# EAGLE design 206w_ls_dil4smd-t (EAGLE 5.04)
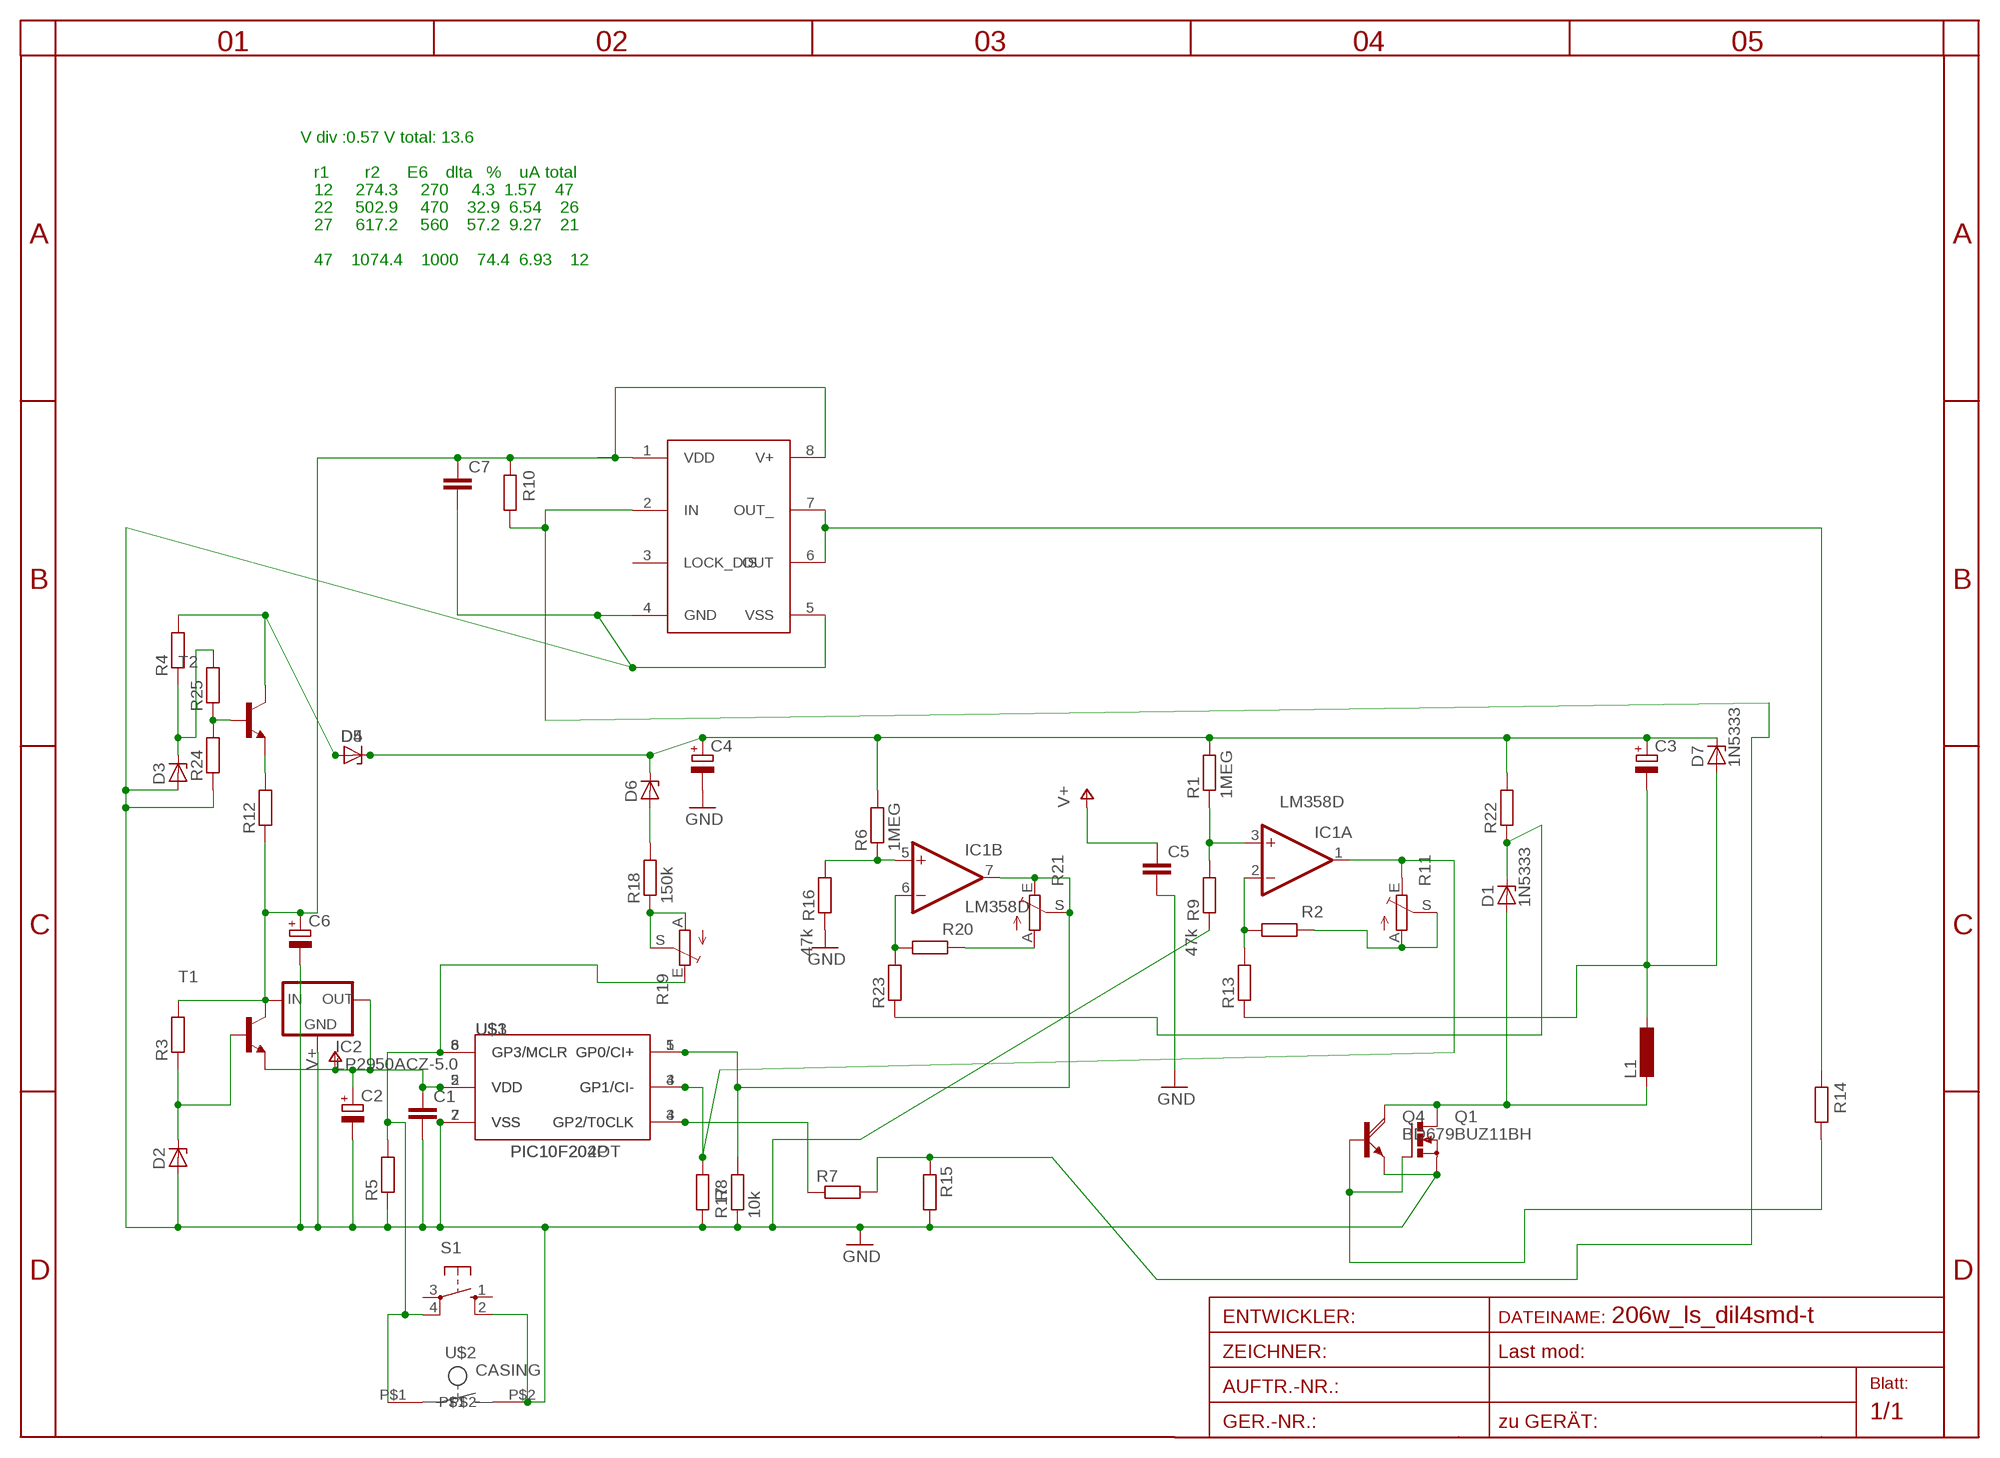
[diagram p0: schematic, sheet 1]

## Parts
C1  C-EUC1206  [C1206]
C2  CPOL-EUSANYO_SMD_E12  [SANYO-OSCON_SMD_E12]
C3  CPOL-EUE5-8.5  [E5-8,5]
C4  CPOL-EUE5-8.5  [E5-8,5]
C5  C-EUC1206  [C1206]
C6  CPOL-EUSANYO_SMD_E12  [SANYO-OSCON_SMD_E12]
C7  C-EUC1206  [C1206]
D1  1N5333  [C1702-15]
D2  ZENER-DIODESOT23  [SOT23]
D3  ZENER-DIODESMB  [SMB]
D4  ZENER-DIODESMB  [SMB]
D5  ZENER-DIODESMB  [SMB]
D6  ZENER-DIODESMB  [SMB]
D7  1N5333  [C1702-15]
IC1  LM358D  [SO08]
IC2  LP2950ACZ-5.0  [TO92]
IC3  TC4432X  [SO-08]
L1  L-EU2200-15.24  [2200-15.24]
Q1  BUZ11BH  [TO220BH]
Q4  BD679  [TO126AV]
R1  1MEG  R-EU_R1206  [R1206]
R2  R-EU_R0805  [R0805]
R3  R-EU_R0805  [R0805]
R4  R-EU_R0805  [R0805]
R5  R-EU_R0805  [R0805]
R6  1MEG  R-EU_R1206  [R1206]
R7  R-EU_R0805  [R0805]
R8  R-EU_R0805  [R0805]
R9  47k  R-EU_R0805  [R0805]
R10  R-EU_R0805  [R0805]
R11  TRIM_EU-CA6V  [CA6V]
R12  R-EU_R0805  [R0805]
R13  R-EU_R1206  [R1206]
R14  R-EU_0207/10  [0207/10]
R15  R-EU_R0805  [R0805]
R16  47k  R-EU_R0805  [R0805]
R17  10k  R-EU_R0805  [R0805]
R18  150k  R-EU_R1206  [R1206]
R19  TRIM_EU-CA6V  [CA6V]
R20  R-EU_R0805  [R0805]
R21  TRIM_EU-CA6V  [CA6V]
R22  R-EU_0309/12  [0309/12]
R23  R-EU_R1206  [R1206]
R24  R-EU_R0805  [R0805]
R25  R-EU_R0805  [R0805]
S1  10-XX  [B3F-10XX]
T1  BC846BLT1-NPN-SOT23-BEC  [SOT23-BEC]
T2  BC846BLT1-NPN-SOT23-BEC  [SOT23-BEC]
U$1  PIC10F202OT  [SOT23-6]
U$2  CASING  [CASING]
U$3  PIC10F204P  [DIL8]

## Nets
BB: IC3.2(IN) R7.2 R10.1 R15.1
GATE: Q1.G Q4.B R14.1
GND: C1.2 C2.- C4.- C5.2 C6.- C7.2 D2.1(A) D3.A IC2.2(GND) IC3.4(GND) IC3.5(VSS) Q1.S Q4.E R5.1 R8.1 R9.1 R15.2 R16.1 R17.1 R24.1 S1.2(S1) U$1.2(VSS) U$2.P$2 U$3.7(VSS)
HOT2: D1.C R22.1 R23.1
HOTSPOT: D1.A L1.2 Q1.D Q4.C
N$1: R2.1 R11.A R11.S
N$2: IC1.1(A:OUT) R8.2 R11.E U$1.3(GP1/CI-) U$3.4(GP1/CI-)
N$5: IC1.5(B:+IN) R6.1 R16.2
N$6: D2.3(C) R3.1 T1.B
N$7: R5.2 R19.E S1.4(P1) U$1.6(GP3/MCLR) U$2.P$1 U$3.8(GP3/MCLR)
N$8: IC1.3(A:+IN) R1.1 R9.2
N$9: R7.1 U$1.4(GP2/T0CLK) U$3.3(GP2/T0CLK)
N$10: R24.2 R25.1 T2.B
N$11: IC3.6(OUT) IC3.7(OUT_) R14.2
N$12: D3.C R4.1 R25.2
N$13: R18.1 R19.A R19.S
N$14: IC1.7(B:OUT) R17.2 R21.E R21.S U$1.1(GP0/CI+) U$3.5(GP0/CI+)
N$15: IC1.2(A:-IN) R2.2 R13.2
N$21: D4.A D5.A R4.2 T2.C
N$22: R12.2 T2.E
N$23: D6.A R18.2
N$24: IC1.6(B:-IN) R20.2 R23.2
N$25: R20.1 R21.A
V60: C3.+ C4.+ D4.C D5.C D6.C D7.C R1.2 R6.2 R22.2
V+: C1.1 C2.+ C5.1 IC2.1(OUT) T1.E U$1.5(VDD) U$3.2(VDD)
VCC: C6.+ C7.1 IC2.3(IN) IC3.1(VDD) IC3.8(V+) R3.2 R10.2 R12.1 T1.C
VOUT: C3.- D7.A L1.1 R13.1
Unconnected: IC3.3(LOCK_DIS) S1.1(S) S1.3(P)

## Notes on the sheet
- V div :0.57 V total: 13.6
- r1        r2      E6    dlta   %    uA total
- 12     274.3     270     4.3  1.57    47
- 22     502.9     470    32.9  6.54    26
- 27     617.2     560    57.2  9.27    21
- 47    1074.4    1000    74.4  6.93    12

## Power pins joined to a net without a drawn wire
GND: IC1.4(P:V-)
V+: IC1.8(P:V+)

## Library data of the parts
C1 C5 C7 = rcl:C-EU: CAPACITOR, European symbol
C2-C4 C6 = rcl:CPOL-EU: POLARIZED CAPACITOR, European symbol
D1 D7 = diode-1:1N5333: Z DIODE
D2-D6 = diode-1:ZENER-DIODE: Z-Diode
IC1 = linear4:LM358: OP AMP
IC2 = v-reg:LP2950?*: Source: http://cache.national.com/ds/LP/LP2950.pdf
IC3 = microchip:TC4432
L1 = rcl:L-EU: INDUCTOR, European symbol
Q1 = transistor-power:BUZ11: N-CHANNEL MOS FET
Q4 = transistor-power:BD679: NPN DARLINGTON TRANSISTOR
R1-R6 R8-R10 R12 R14-R16 R20 R24 R25 = rcl:R-EU_: RESISTOR, European symbol
R7 R13 R17 R18 R22 R23 = rcl-2:R-EU_: RESISTOR, European symbol
R11 R19 R21 = pot:TRIM_EU-: POTENTIOMETER
S1 = switch-omron:10-XX: OMRON SWITCH
T1 T2 = transistor-neu-to92:*-NPN-: NPN Transistror
U$1 U$3 = microchip-5:PIC10F2*: uPC nW 0,25/0,5k Program Flash memory Comparator
U$2 = button:CASING

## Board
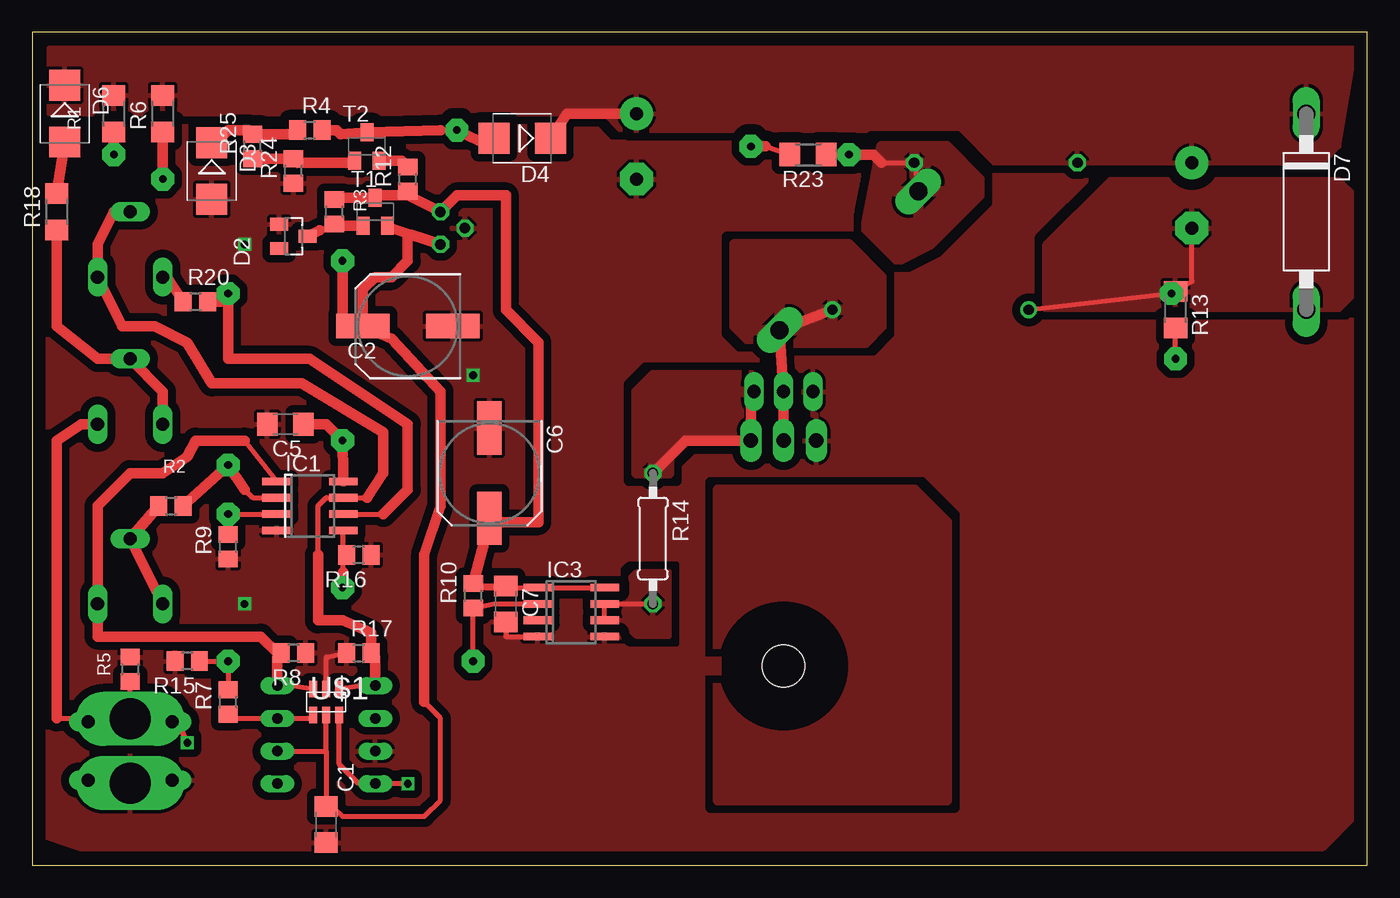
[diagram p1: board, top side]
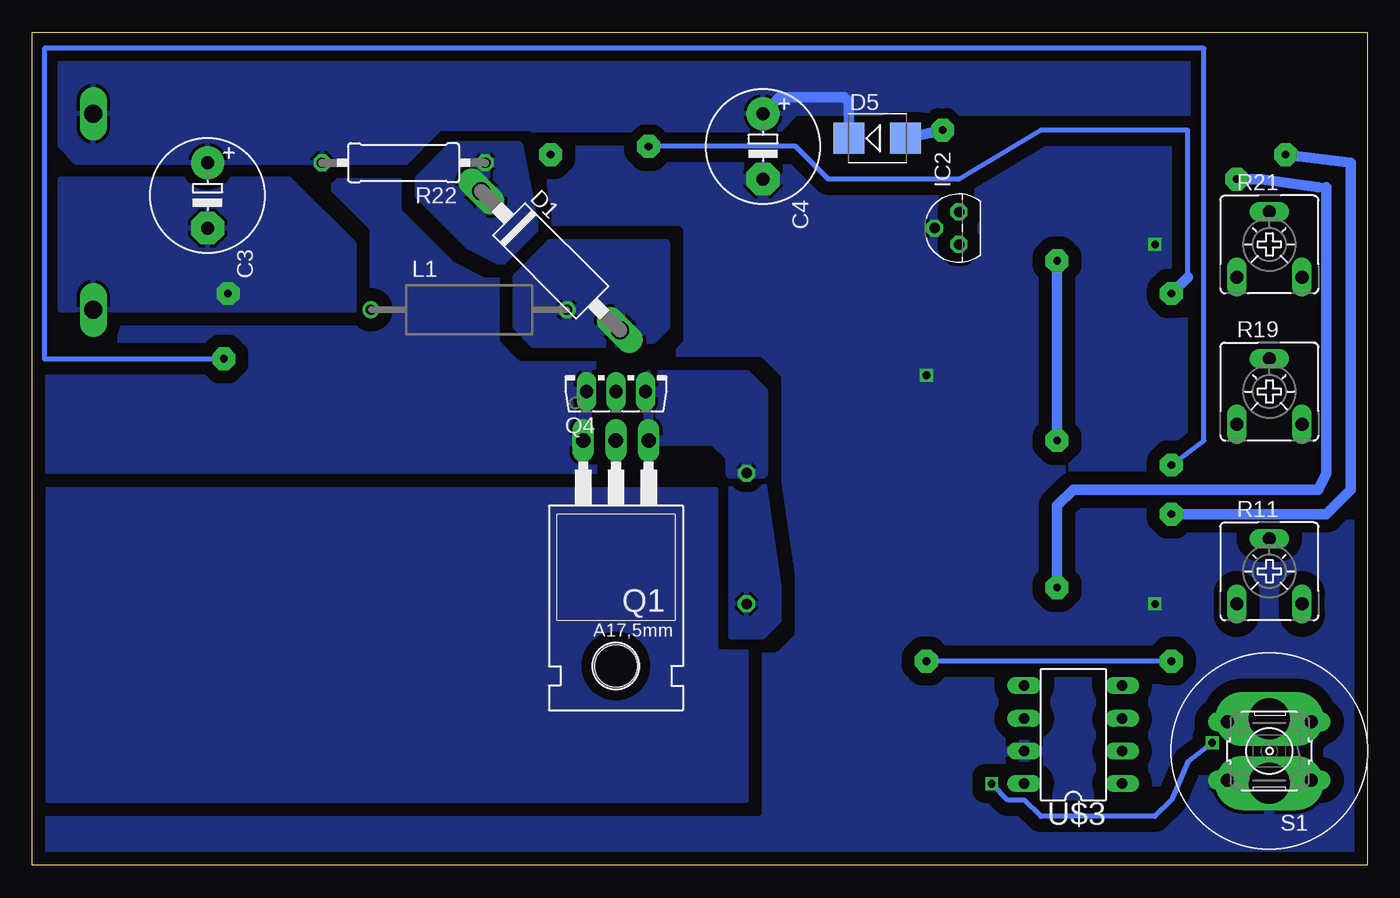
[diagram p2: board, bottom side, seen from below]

Size 103.81 x 64.76 mm. Coordinates in mm from the lower left corner, seen from the top.
Outline: 0,0 103.81,0 103.81,64.76 0,64.76 0,0
Copper layers (1*16): Top 0.035mm / dielectric 1.5mm / Bottom 0.035mm
Design rules "default": minimum track width 10mil, minimum drill 24mil, track to track 8mil, track to pad 8mil, pad to pad 8mil, via to via 8mil, smd to smd 8mil, copper to edge 40mil, drill to drill 8mil, minimum pad ring 10mil, minimum via ring 8mil, stop-mask expansion 4mil, vias tented up to drill 0mil, thermal gap 10mil

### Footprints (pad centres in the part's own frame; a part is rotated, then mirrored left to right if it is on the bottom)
C1206 = smd 1.6 x 1.8: 1 -1.4,0; 2 1.4,0
SANYO-OSCON_SMD_E12 = smd 4.15 x 1.9: + 3.5,0; - -3.5,0
E5-8,5 = drill 1.016 pad 2.54 round: + -2.54,0 | drill 1.016 pad 2.54 octagon: - 2.54,0
C1702-15 = drill 1.397 long: A 7.62,0; C -7.62,0
SOT23 = smd 1 x 1.4: 1 -0.95,-1.1; 2 0.95,-1.1; 3 0,1.1
SMB = smd 2.4 x 2.4: A 2.2,0; C -2.2,0
SO08 = smd 0.6 x 2.2: 1 -1.905,-2.6; 2 -0.635,-2.6; 3 0.635,-2.6; 4 1.905,-2.6; 5 1.905,2.6; 6 0.635,2.6; 7 -0.635,2.6; 8 -1.905,2.6
TO92 = drill 0.813 octagon: 1 -1.27,0; 2 0,1.905; 3 1.27,0
SO-08 = smd 0.6 x 2.2: 1 -1.905,-2.6; 2 -0.635,-2.6; 3 0.635,-2.6; 4 1.905,-2.6; 5 1.905,2.6; 6 0.635,2.6; 7 -0.635,2.6; 8 -1.905,2.6
2200-15.24 = drill 0.8 pad 1.27 round: 1 -7.62,0; 2 7.62,0
TO220BH = drill 1.118 long: D 0,-6.35; G -2.54,-6.35; S 2.54,-6.35 | hole 3.302: 0,11.176
TO126AV = drill 1.016 long: B 2.286,-1.27; C 0,-1.27; E -2.286,-1.27
R1206 = smd 1.6 x 1.803: 1 -1.422,0; 2 1.422,0
R0805 = smd 1.3 x 1.5: 1 -0.95,0; 2 0.95,0
CA6V = drill 1.016 long: A -2.54,-2.54; E 2.54,-2.54; S 0,2.54
0207/10 = drill 0.813 octagon: 1 -5.08,0; 2 5.08,0
0309/12 = drill 0.813 octagon: 1 -6.35,0; 2 6.35,0
B3F-10XX = drill 1.016 long: 1 -3.251,2.261; 2 3.251,2.261; 3 -3.251,-2.261; 4 3.251,-2.261
SOT23-BEC = smd 1 x 1.4: B -0.95,-1.1; C 0,1.1; E 0.95,-1.1
SOT23-6 = smd 0.635 x 1.27: 1 -1.016,-1.016; 2 0,-1.016; 3 1.016,-1.016; 4 1.016,1.016; 5 0,1.016; 6 -1.016,1.016
CASING = drill 3.2 pad 3.81 long: P$1 -2.5,0; P$2 2.5,0
DIL8 = drill 0.813 long: 1 -3.81,-3.81; 2 -1.27,-3.81; 3 1.27,-3.81; 4 3.81,-3.81; 5 3.81,3.81; 6 1.27,3.81; 7 -1.27,3.81; 8 -3.81,3.81

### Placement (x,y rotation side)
C1  22.86,3.17 270 top
C2  29.21,41.91 180 top
C3  90.17,52.07 270 bottom
C4  46.99,55.88 270 bottom
C5  19.68,34.29 180 top
C6  35.56,30.48 270 top
C7  36.83,20.32 270 top
D1  63.5,46.99 315 bottom
D2  20.32,48.9 270 top
D3  13.97,53.98 270 top
D4  38.1,56.52 180 top
D5  38.1,56.52 0 bottom
D6  2.54,58.42 270 top
D7  99.06,50.8 270 top
IC1  21.59,27.94 270 top
IC2  31.75,49.53 90 bottom
IC3  41.91,19.68 270 top
L1  69.85,43.18 0 bottom
Q1  58.42,26.67 180 bottom
Q4  58.42,38.1 0 bottom
R1  6.35,58.42 90 top
R2  10.79,27.94 0 top
R3  23.5,50.8 90 top
R4  21.59,57.15 0 top
R5  7.62,15.24 270 top
R6  10.16,58.42 90 top
R7  15.24,12.7 90 top
R8  20.32,16.51 180 top
R9  15.24,24.77 90 top
R10  34.29,20.95 90 top
R11  7.62,22.86 0 bottom
R12  29.21,53.34 90 top
R13  88.9,43.18 270 top
R14  48.26,25.4 270 top
R15  12.06,15.88 180 top
R16  25.4,24.13 180 top
R17  25.4,16.51 0 top
R18  1.91,50.8 90 top
R19  7.62,36.83 0 bottom
R20  12.7,43.81 0 top
R21  7.62,48.26 0 bottom
R22  74.93,54.61 180 bottom
R23  60.33,55.24 180 top
R24  20.32,53.98 90 top
R25  17.14,55.88 90 top
S1  7.62,8.89 180 bottom
T1  26.67,50.8 0 top
T2  26.04,55.88 0 top
U$1  22.86,12.7 180 top
U$2  7.62,8.89 270 bottom
U$3  22.86,10.16 90 bottom

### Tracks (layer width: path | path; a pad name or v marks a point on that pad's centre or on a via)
BB  (via drill 0.6 pad 1.78)
  Top 0.406: IC3.2 35.88,20.32 R10.1 v34.29,15.88 | R7.2 v15.24,15.88 R15.1
  Bottom 0.406: v15.24,15.88 v34.29,15.88
GATE
  Top 0.406: 55.88,36.58 Q4.B
  Top 0.813: R14.1 50.8,33.02 Q1.G 55.88,36.58
  pour Top: 55.88,38.1 48.26,38.1 46.99,36.83 46.99,30.48 49.53,30.48 49.53,31.75 50.8,33.02 55.88,33.02
  pour Bottom: 55.88,38.1 48.26,38.1 46.99,36.83 46.99,30.48 49.53,30.48 49.53,31.75 50.8,33.02 55.88,33.02
GND  (via drill 0.6)
  Top 0.406: C7.2 36.83,17.78 IC3.4 | U$1.2 22.86,16.19 R17.1
  other vias: 16.51,48.26 16.51,20.32 34.29,38.1
  pour Bottom (isolate 1.016, rank 5): 102.87,60.96 102.87,0 90.17,0 1.27,1.27 1.27,53.34 1.27,58.42
  pour Top (isolate 0.61, rank 5): 1.27,63.5 99.06,63.5 102.87,59.69 102.87,3.81 100.33,1.27 3.81,1.27 0,2.54
HOT2  (via drill 0.6 pad 1.78)
  Top 0.406: R23.1 v63.5,55.24 | 66.04,54.61 R22.1 D1.C
  Top 0.813: v63.5,55.24 65.41,55.24 66.04,54.61
  pour Top (rank 2): 66.04,55.88 71.12,55.88 73.66,53.34 73.66,52.07 69.85,48.26 67.31,46.99 64.77,49.53
  pour Bottom (rank 2): 66.04,55.88 71.12,55.88 73.66,53.34 73.66,52.07 69.85,48.26 67.31,46.99 64.77,49.53
HOTSPOT
  Top 0.813: L1.2 D1.A Q4.C Q1.D
  pour Top: 54.61,48.26 63.5,48.26 66.04,45.72 66.04,41.91 64.77,40.64 55.88,40.64 54.61,41.91
  pour Bottom: 54.61,48.26 63.5,48.26 66.04,45.72 66.04,41.91 64.77,40.64 55.88,40.64 54.61,41.91
N$1
  Top 0.813: R11.A R11.S R2.1
N$2
  Top 0.406: 16.51,33.02 IC1.1 | U$1.3 20.32,13.97 U$3.4 | 19.05,16.19 R8.2 19.05,16.51
  Top 0.813: 16.51,33.02 12.7,33.02 12.06,31.75 10.16,30.48 7.62,30.48 5.08,27.94 R11.E 5.08,17.78 17.78,17.78 19.05,16.51 | 19.05,16.19 U$3.4
N$5  (via drill 0.6 pad 1.78)
  Top 0.406: 24.19,24.39 R16.2 | 24.19,22.8 24.19,24.39 | 24.19,24.39 IC1.5
  Top 0.813: v10.16,53.34 R6.1 | v24.13,21.59 24.19,22.8
  Bottom 0.61: 3.17,52.7 3.81,52.7
  Bottom 0.813: v10.16,53.34 8.26,53.34 3.81,52.7 | 3.17,52.7 3.17,30.48 3.81,29.21 22.86,29.21 24.13,27.94 v24.13,21.59
N$6
  Top 0.406: 23.64,49.7 R3.1 22.37,49.36
  Top 0.813: 23.64,49.7 T1.B | D2.3 22.37,49.36
N$7  (via drill 0.6)
  Top 0.406: 1.91,11.43 7.58,11.43 U$2.P$1 | U$2.P$1 10.79,10.79 10.16,10.44 S1.4 11.15,11.43 v12.06,9.53 | U$1.6 23.88,7.87 25.4,6.35 U$3.8 v29.21,6.35 | U$2.P$1 R5.2
  Top 0.813: R19.E 3.81,34.29 1.91,33.02 1.91,11.43
  Bottom 0.406: v29.21,6.35 27.94,5.08 26.67,5.08 25.4,3.81 16.51,3.81 15.24,5.08 13.97,8.05 v12.06,9.53
N$8  (via drill 0.6 pad 1.78)
  Top 0.406: IC1.3 15.56,27.3 R9.2 v15.24,27.3
  Top 0.813: v6.35,55.24 R1.1
  Bottom 0.813: v6.35,55.24 1.27,54.61 1.27,29.21 3.17,27.3 v15.24,27.3
N$9
  Top 0.406: R7.1 15.56,11.43 U$3.3 21.59,11.43 U$1.4
N$10
  Top 0.406: 24.77,54.61 T2.B
  Top 0.813: 24.77,54.61 20.64,54.61 R24.2 R25.1
N$11
  Top 0.406: R14.2 IC3.7 IC3.6
  pour Bottom (isolate 0.813): 45.72,21.59 46.99,30.48 49.53,30.48 49.53,17.78 46.99,17.78 45.72,19.05
  pour Top (isolate 0.813): 45.72,21.59 46.99,22.86 49.53,22.86 49.53,17.78 46.99,17.78 45.72,19.05
N$12
  Top 0.406: D3.C 13.97,55.88
  Top 0.813: D3.C 14.27,56.17 15.24,57.15 16.82,57.15 R25.2 20.32,56.83 R4.1
N$13
  Top 0.813: R18.1 1.91,41.91 5.08,39.37 R19.S 10.16,36.83 R19.A
N$14
  Top 0.406: 26.04,28.57 IC1.7 22.86,28.57 22.23,27.94 22.23,24.13 | 26.67,16.19 R17.2 | U$1.1 25.4,13.97 U$3.5
  Top 0.813: 26.04,28.57 27.3,30.48 27.3,33.66 20.95,37.47 13.97,37.47 12.06,40.64 9.53,41.91 6.99,41.91 R21.E 5.08,48.26 6.35,50.8 R21.S | R17.2 26.35,18.1 24.13,19.05 22.23,19.05 22.23,24.13 | U$3.5 26.67,16.19
N$15  (via drill 0.6 pad 1.78)
  Top 0.406: 16.51,29.21 17.14,28.57 IC1.2 | v88.9,39.37 R13.2
  Top 0.813: 16.51,29.21 v15.24,31.11 R2.2
  Bottom 0.406: v88.9,39.37 102.87,39.37 102.87,63.5 12.7,63.5 12.7,33.02 v15.24,31.11
N$20
  pour Top (isolate 0.813, rank 3): 53.34,29.21 68.58,29.21 71.12,26.67 71.12,5.08 53.34,5.08
  pour Bottom (isolate 0.813, rank 3): 48.26,29.21 102.87,29.21 102.87,5.08 48.26,5.08
N$21  (via drill 0.6 pad 1.78)
  Top 0.406: 35.56,55.88 D5.A | 31.75,57.15 v33.02,57.15
  Top 0.813: v33.02,57.15 35.56,55.88 | 31.75,57.15 T2.C 23.98,56.83 23.66,57.15 R4.2
  Bottom 0.813: v33.02,57.15 D5.A
N$22
  Top 0.813: T2.E 28.72,54.78 R12.2
N$23
  Top 0.813: R18.2 D6.A
N$24  (via drill 0.6 pad 1.78)
  Top 0.406: 57,55.88 R23.2 | IC1.6 27.3,27.3
  Top 0.813: v55.88,55.88 57,55.88 | 27.3,27.3 29.21,29.21 29.21,34.29 21.59,39.37 15.24,39.37 v15.24,44.45 14.61,43.81 R20.2
  Bottom 0.406: v55.88,55.88 44.45,55.88 41.91,53.34 31.75,53.34 25.4,57.15 13.97,57.15 13.97,45.72
  Bottom 0.813: v15.24,44.45 13.97,45.72
N$25
  Top 0.813: R21.A 10.48,45.72 R20.1
V60
  Top 0.813: C4.+ 41.57,58.42 D5.C
  Bottom 0.813: D5.C 40.3,59.35 40.64,59.69 45.72,59.69 C4.+
  pour Top (isolate 0.813, rank 4): 102.87,63.5 1.27,63.5 1.27,58.42 44.45,58.42 45.72,57.15 71.12,57.15 73.66,54.61 100.33,54.61 101.6,55.88
  pour Bottom (isolate 0.813, rank 4): 102.87,63.5 1.27,63.5 1.27,48.26 7.62,48.26 7.62,54.61 6.35,55.88 6.35,57.15 7.62,58.42 44.45,58.42 45.72,57.15 71.12,57.15 73.66,54.61 100.33,54.61 101.6,55.88
V+  (via drill 0.6 pad 1.78)
  Top 0.406: C2.+ 24.13,41.91 | IC1.8 24.13,29.91 | 27.94,49.53 T1.E | U$3.2 22.86,8.89 | 22.86,8.89 U$1.5 | 30.48,12.7 31.75,11.43 31.75,5.08 30.48,3.81 24.13,3.81 23.5,4.45 22.99,4.45 C1.1 22.86,8.89
  Top 0.813: 27.79,49.53 27.94,49.53 29.46,49.02 | 29.46,49.02 IC2.1 | 30.48,12.7 30.48,24.13 31.75,27.94 31.75,36.83 27.94,40.95 C2.+ 25.71,44.76 26.67,45.72 27.94,45.72 29.21,46.99 29.21,48.77 29.46,49.02 | IC1.8 24.19,30.42 v24.13,33.02 22.86,34.29 C5.1 | 24.13,41.91 v24.13,46.99
  Bottom 0.813: v24.13,46.99 v24.13,33.02
VCC
  Top 0.406: IC3.8 IC3.1 35.24,21.59 R10.2 34.29,21.72 C7.1 | 35.56,26.67 C6.+ | 26.84,52.07 T1.C | 23.64,51.9 R3.2
  Top 0.813: R10.2 35.56,26.67 39.37,26.67 39.37,40.64 36.83,43.18 36.83,52.07 33.02,52.07 IC2.3 29.21,52.07 | T1.C 23.64,51.9 | 29.21,52.07 26.84,52.07 | 29.21,52.07 R12.1
VOUT  (via drill 0.6 pad 1.78)
  Top 0.406: L1.1 v88.58,44.45 R13.1 90.17,45.4 C3.-
  pour Top (isolate 0.813, rank 3): 101.6,53.34 102.87,52.07 102.87,44.45 101.6,43.18 78.74,43.18 78.74,48.26 83.82,53.34
  pour Bottom (isolate 0.813, rank 3): 101.6,53.34 102.87,52.07 102.87,44.45 101.6,43.18 78.74,43.18 78.74,48.26 83.82,53.34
